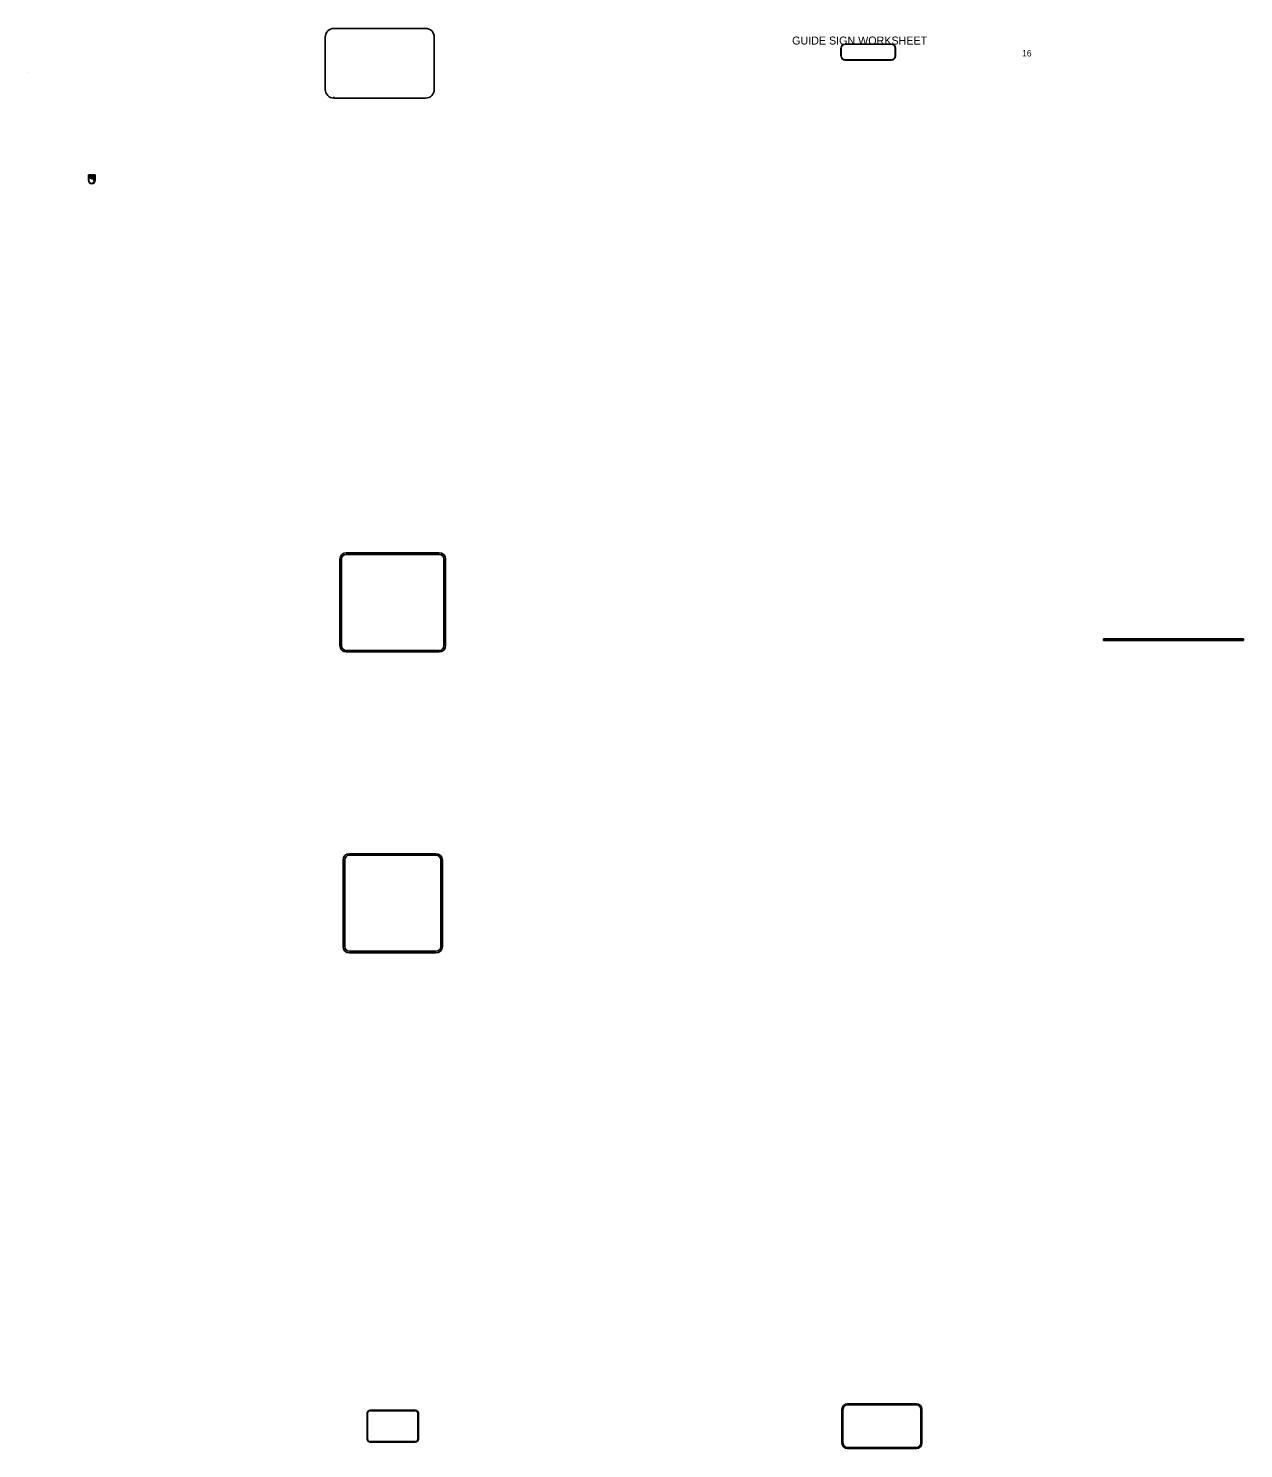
# Model space of a CAD drawing. Extents: x 10268197 to 10268511, y 2141503 to 2142677.
# Drawn here: x 10268312.2 to 10268502, y 2142156.5 to 2142378.2 of the extents above; entities that cross this region are included whole.
import ezdxf

# ---------------------------------------------------------------- set-up
doc = ezdxf.new("R2010")
doc.units = 0
for name, color, linetype in [('AdhocPoint_dp', 7, 'Continuous'), ('GSColorFill', 7, 'Continuous'), ('GSOutline', 7, 'Continuous'), ('TextMisc', 7, 'Continuous'), ('TextShtNo', 7, 'Continuous')]:
    doc.layers.add(name, color=color, linetype=linetype)

msp = doc.modelspace()

# ---------------------------------------------------------------- linework, layer by layer
at = {"layer": 'AdhocPoint_dp'}
msp.add_line((10268312.23, 2142371.28), (10268312.23, 2142371.28), dxfattribs=at)
at = {"layer": 'GSColorFill'}
for p, q in [((10268358.57, 2142376.85), (10268358.57, 2142368.68)), ((10268374.23, 2142378.21), (10268359.93, 2142378.21)), ((10268375.59, 2142368.68), (10268375.59, 2142376.85)), ((10268439.1, 2142375.11), (10268439.1, 2142373.94)), ((10268439.1, 2142375.11), (10268439.1, 2142373.94)), ((10268439.12, 2142373.94), (10268439.12, 2142375.11)), ((10268446.93, 2142375.77), (10268439.77, 2142375.77)), ((10268446.93, 2142375.77), (10268439.77, 2142375.77)), ((10268439.77, 2142375.76), (10268446.93, 2142375.76)), ((10268447.58, 2142375.11), (10268447.58, 2142373.94)), ((10268447.6, 2142373.94), (10268447.6, 2142375.11)), ((10268447.6, 2142373.94), (10268447.6, 2142375.11)), ((10268439.77, 2142373.27), (10268439.77, 2142373.29)), ((10268446.93, 2142373.29), (10268439.77, 2142373.29)), ((10268439.77, 2142373.29), (10268439.77, 2142373.27)), ((10268439.77, 2142373.27), (10268446.93, 2142373.27)), ((10268439.77, 2142373.27), (10268446.93, 2142373.27)), ((10268359.93, 2142367.32), (10268359.93, 2142367.55)), ((10268359.93, 2142367.55), (10268359.93, 2142367.32)), ((10268359.93, 2142367.32), (10268374.23, 2142367.32))]:
    msp.add_line(p, q, dxfattribs=at)
for points in [[(10268321.6, 2142355.3), (10268321.6, 2142354.52)], [(10268321.6, 2142354.52), (10268321.6, 2142355.3)], [(10268321.61, 2142355.3), (10268321.61, 2142354.52)], [(10268322.62, 2142355.3), (10268322.62, 2142355.03), (10268321.64, 2142355.03), (10268321.64, 2142355.3)], [(10268321.64, 2142354.52), (10268321.64, 2142355.01), (10268322.62, 2142355.01), (10268322.62, 2142354.52)], [(10268322.6, 2142355.36), (10268321.66, 2142355.36)], [(10268321.66, 2142355.36), (10268322.6, 2142355.36)], [(10268321.66, 2142355.32), (10268322.13, 2142355.32), (10268322.13, 2142355.34), (10268321.66, 2142355.34)], [(10268321.68, 2142354.96), (10268321.69, 2142354.95)], [(10268321.71, 2142354.88), (10268321.71, 2142354.88)], [(10268321.71, 2142354.88), (10268321.71, 2142354.88)], [(10268321.97, 2142354.91), (10268322.25, 2142354.87)], [(10268322.27, 2142354.89), (10268321.98, 2142354.93)], [(10268322.59, 2142355.34), (10268322.13, 2142355.34), (10268322.13, 2142355.32), (10268322.59, 2142355.32)], [(10268322.28, 2142354.87), (10268322.28, 2142354.87)], [(10268322.31, 2142354.87), (10268322.31, 2142354.87)], [(10268322.33, 2142354.91), (10268322.32, 2142354.92)], [(10268322.32, 2142354.9), (10268322.33, 2142354.89)], [(10268322.34, 2142354.86), (10268322.36, 2142354.76)], [(10268322.38, 2142354.76), (10268322.36, 2142354.87)], [(10268322.39, 2142354.69), (10268322.4, 2142354.67)], [(10268322.42, 2142354.68), (10268322.41, 2142354.7)], [(10268322.64, 2142354.52), (10268322.64, 2142355.3)], [(10268322.65, 2142354.52), (10268322.65, 2142355.3)], [(10268322.65, 2142355.3), (10268322.65, 2142354.52)], [(10268322.13, 2142353.97), (10268322.13, 2142353.99)], [(10268322.13, 2142353.99), (10268322.13, 2142353.97), (10268322.13, 2142353.97)], [(10268322.13, 2142353.95), (10268322.13, 2142353.95)], [(10268322.13, 2142353.95), (10268322.13, 2142353.95)], [(10268322.13, 2142353.95), (10268322.13, 2142353.95)], [(10268322.17, 2142354.65), (10268322.19, 2142354.66)], [(10268322.35, 2142354.19), (10268322.33, 2142354.18)], [(10268322.39, 2142354.17), (10268322.38, 2142354.16)], [(10268322.39, 2142354.14), (10268322.4, 2142354.15)], [(10268322.42, 2142354.64), (10268322.44, 2142354.6)], [(10268322.46, 2142354.61), (10268322.43, 2142354.65)], [(10268322.45, 2142354.57), (10268322.46, 2142354.53)], [(10268322.48, 2142354.53), (10268322.47, 2142354.58)]]:
    msp.add_lwpolyline(points, dxfattribs=at)
for centre, radius, start, end in [((10268359.93, 2142376.85), 1.36, 90, 180), ((10268374.23, 2142376.85), 1.36, 0, 90), ((10268439.77, 2142375.11), 0.667, 90, 180), ((10268439.77, 2142375.11), 0.667, 90, 180), ((10268439.77, 2142375.11), 0.65, 90, 180), ((10268446.93, 2142375.11), 0.667, 0, 90), ((10268446.93, 2142375.11), 0.667, 0, 90), ((10268446.93, 2142375.11), 0.65, 0, 90), ((10268439.77, 2142373.94), 0.667, 180, 270), ((10268439.77, 2142373.94), 0.667, 180, 270), ((10268439.77, 2142373.94), 0.65, 180, 270), ((10268446.93, 2142373.94), 0.667, 270, 0), ((10268446.93, 2142373.94), 0.65, 270, 0), ((10268446.93, 2142373.94), 0.667, 270, 0), ((10268359.93, 2142368.68), 1.36, 180, 270), ((10268374.23, 2142368.68), 1.36, 270, 0)]:
    msp.add_arc(centre, radius, start, end, dxfattribs=at)
for centre, major_axis, start_param, end_param in [((10268321.66, 2142355.29), (0, 0.0703), 0.098213, 1.408003), ((10268321.66, 2142355.29), (0, 0.0705), 0.098082, 1.408221), ((10268321.66, 2142355.29), (0, 0.0529), 0.11327, 1.383001), ((10268321.66, 2142355.29), (0, 0.0294), 0.152033, 1.318544), ((10268321.65, 2142355), (0, 0.026), 4.051262, 4.587994), ((10268322.03, 2142354.81), (0, 0.418), 1.148552, 1.171978), ((10268321.67, 2142354.97), (0, 0.00205), 1.350308, 3.382945), ((10268321.67, 2142354.97), (0, 0.0033), 5.257186, 6.472249), ((10268321.63, 2142354.94), (0, 0.0535), 5.170612, 5.366939), ((10268322.1, 2142358.79), (0, 3.82), 3.0228, 3.102998), ((10268321.68, 2142354.96), (0, 0.00167), 1.876358, 3.458947), ((10268321.68, 2142354.96), (0, 0.0023), 5.006675, 6.675737), ((10268321.68, 2142354.91), (0, 0.00646), 3.672662, 4.871849), ((10268321.69, 2142354.89), (0, 0.0123), 0.633597, 2.648042), ((10268321.69, 2142354.96), (0, 0.00328), 1.878733, 3.108176), ((10268321.69, 2142354.94), (0, 0.00855), 5.256742, 6.115579), ((10268321.69, 2142354.95), (0, 0.00333), 4.486807, 5.309085), ((10268321.78, 2142354.91), (0, 0.0999), 1.186151, 1.539742), ((10268321.7, 2142354.92), (0, 0.0377), 2.867281, 3.188718), ((10268321.7, 2142354.81), (0, 0.0733), 6.061742, 6.254182), ((10268321.69, 2142354.94), (0, 0.032), 5.272311, 5.523753), ((10268322.1, 2142358.79), (0, 3.85), 3.031956, 3.0986), ((10268321.69, 2142354.95), (0, 0.0268), 4.38027, 5.281838), ((10268321.78, 2142354.91), (0, 0.0764), 1.174629, 1.522814), ((10268321.92, 2142355.5), (0, 0.629), 2.775496, 2.836), ((10268321.68, 2142354.91), (0, 0.03), 4.660636, 4.76546), ((10268321.71, 2142354.88), (0, 0.000638), 2.840072, 4.276704), ((10268321.71, 2142354.88), (0, 0.000524), 5.987968, 7.518423), ((10268321.92, 2142355.5), (0, 0.652), 2.795567, 2.837701), ((10268321.76, 2142354.98), (0, 0.081), 2.935797, 3.111869), ((10268321.76, 2142354.98), (0, 0.105), 2.923962, 3.100366), ((10268321.69, 2142354.34), (0, 0.533), 6.086214, 6.156313), ((10268321.69, 2142354.34), (0, 0.556), 6.084521, 6.158258), ((10268321.8, 2142354.92), (0, 0.0309), 2.852504, 3.366789), ((10268321.8, 2142354.92), (0, 0.0544), 2.874985, 3.359529), ((10268321.82, 2142354.81), (0, 0.0792), 6.040706, 6.480942), ((10268321.82, 2142354.81), (0, 0.0557), 6.026184, 6.476458), ((10268321.81, 2142354.7), (0, 0.185), 5.684781, 6.113431), ((10268321.81, 2142354.7), (0, 0.161), 5.697067, 6.119013), ((10268322.01, 2142354.97), (0, 0.181), 2.375, 2.467209), ((10268321.9, 2142354.82), (0, 0.00159), 5.485297, 7.704353), ((10268321.92, 2142354.81), (0, 0.0255), 0.964156, 2.090382), ((10268321.91, 2142354.8), (0, 0.00569), 1.939097, 3.308145), ((10268322.01, 2142354.97), (0, 0.157), 2.362414, 2.445308), ((10268321.9, 2142354.82), (0, 0.0121), 4.628672, 6.022596), ((10268321.89, 2142354.81), (0, 0.0234), 4.312458, 4.790361), ((10268321.93, 2142354.81), (0, 0.0215), 1.284916, 1.908092), ((10268321.9, 2142354.82), (0, 0.0041), 4.221459, 5.929721), ((10268321.91, 2142354.81), (0, 0.00423), 2.162887, 4.05091), ((10268321.89, 2142354.89), (0, 0.104), 3.297928, 3.510473), ((10268321.9, 2142354.82), (0, 0.0356), 4.927168, 5.844494), ((10268321.94, 2142354.77), (0, 0.0259), 6.114599, 6.726558), ((10268321.95, 2142354.91), (0, 0.09), 3.002553, 3.788583), ((10268321.95, 2142354.91), (0, 0.113), 3.077286, 3.764777), ((10268321.98, 2142354.96), (0, 0.0374), 2.044108, 2.116391), ((10268321.99, 2142354.95), (0, 0.0489), 1.626511, 2.63302), ((10268321.95, 2142354.96), (0, 0.012), 4.739475, 5.22955), ((10268321.96, 2142354.95), (0, 0.00667), 4.461638, 5.646624), ((10268321.98, 2142354.96), (0, 0.0139), 1.562078, 2.226686), ((10268321.99, 2142354.95), (0, 0.0254), 1.523898, 2.474336), ((10268322.01, 2142354.81), (0, 0.0327), 0.291413, 0.478416), ((10268322.04, 2142354.83), (0, 0.041), 6.01566, 7.397045), ((10268322.03, 2142354.83), (0, 0.0298), 1.091914, 1.118585), ((10268322.01, 2142354.81), (0, 0.00922), 5.412655, 6.623003), ((10268322.03, 2142354.83), (0, 0.00627), 1.057989, 2.418777), ((10268322.03, 2142354.82), (0, 0.0104), 2.169624, 2.636557), ((10268322.03, 2142354.82), (0, 0.00291), 2.447997, 4.324956), ((10268322.04, 2142354.83), (0, 0.0175), 5.90331, 7.414322), ((10268322.02, 2142354.82), (0, 0.00757), 4.18924, 5.624255), ((10268322.06, 2142354.84), (0, 0.0282), 6.008573, 6.53107), ((10268322.05, 2142354.85), (0, 0.00632), 2.333666, 3.623187), ((10268322.06, 2142354.84), (0, 0.00472), 6.020224, 7.210209), ((10268322.03, 2142354.75), (0, 0.12), 5.371864, 6.001104), ((10268322.03, 2142354.75), (0, 0.0962), 5.382216, 5.999852), ((10268322.03, 2142354.76), (0, 0.0905), 5.020599, 5.276447), ((10268322.14, 2142354.81), (0, 0.0366), 2.049296, 2.415522), ((10268322.03, 2142354.76), (0, 0.114), 5.043581, 5.287393), ((10268322.11, 2142354.76), (0, 0.0216), 4.723898, 5.514452), ((10268322.14, 2142354.81), (0, 0.0132), 2.155604, 2.437858), ((10268322.21, 2142354.77), (0, 0.0926), 1.679569, 1.877594), ((10268322.15, 2142354.75), (0, 0.0211), 1.926422, 2.617636), ((10268322.11, 2142354.76), (0, 0.0451), 4.755633, 5.530169), ((10268322.12, 2142354.7), (0, 0.0371), 4.912404, 5.681954), ((10268322.21, 2142354.77), (0, 0.0691), 1.691953, 1.850237), ((10268322.12, 2142354.7), (0, 0.0606), 4.870438, 5.69492), ((10268322.2, 2142354.71), (0, 0.0466), 1.603254, 2.056889), ((10268322.09, 2142354.65), (0, 0.0815), 4.999681, 5.181626), ((10268322.15, 2142354.67), (0, 0.0125), 4.286383, 5.097358), ((10268322.17, 2142354.66), (0, 0.00829), 1.147713, 2.022718), ((10268322.2, 2142354.71), (0, 0.0231), 1.542583, 2.06345), ((10268322.09, 2142354.65), (0, 0.105), 5.008447, 5.183955), ((10268322.15, 2142354.67), (0, 0.036), 4.58555, 5.059156), ((10268322.15, 2142354.65), (0, 0.0426), 5.101976, 5.271031), ((10268322.27, 2142354.87), (0, 0.0263), 1.495786, 3.039166), ((10268322.19, 2142354.87), (0, 0.0869), 4.732247, 4.878022), ((10268322.28, 2142354.89), (0, 0.00913), 1.352418, 2.01063), ((10268322.26, 2142354.88), (0, 0.00805), 4.379744, 4.814874), ((10268322.28, 2142354.93), (0, 0.0574), 3.035408, 3.204096), ((10268322.27, 2142354.87), (0, 0.00285), 1.109885, 3.045896), ((10268322.28, 2142354.93), (0, 0.0809), 3.036263, 3.109566), ((10268322.28, 2142354.87), (0, 0.0242), 2.680355, 4.018837), ((10268322.28, 2142354.87), (0, 0.000707), 2.226104, 4.018837), ((10268322.28, 2142354.86), (0, 0.00354), 5.664697, 6.296132), ((10268322.3, 2142354.92), (0, 0.00883), 0.407393, 1.224717), ((10268322.29, 2142354.93), (0, 0.00308), 2.554355, 4.582696), ((10268322.32, 2142354.91), (0, 0.0351), 1.15727, 1.990189), ((10268322.27, 2142354.89), (0, 0.0194), 4.289312, 5.031813), ((10268322.32, 2142354.86), (0, 0.0367), 1.060493, 1.42239), ((10268322.28, 2142354.87), (0, 0.00364), 4.143687, 4.652253), ((10268322.33, 2142354.96), (0, 0.0373), 2.364476, 2.623448), ((10268322.3, 2142354.93), (0, 0.00399), 5.525274, 6.621403), ((10268322.28, 2142354.87), (0, 0.0271), 4.143687, 4.589576), ((10268322.29, 2142354.86), (0, 0.0137), 3.974032, 4.188492), ((10268322.31, 2142354.92), (0, 0.0032), 5.726467, 6.786368), ((10268322.31, 2142354.93), (0, 0.0037), 2.763735, 3.701166), ((10268322.27, 2142354.89), (0, 0.0429), 4.289312, 4.979338), ((10268322.32, 2142354.9), (0, 0.00845), 2.088134, 3.055358), ((10268322.32, 2142354.86), (0, 0.0132), 1.060493, 1.394015), ((10268322.32, 2142354.89), (0, 0.0308), 6.107601, 6.199828), ((10268322.31, 2142354.91), (0, 0.0168), 5.307679, 5.799127), ((10268322.34, 2142354.94), (0, 0.0241), 2.956314, 3.451659), ((10268322.34, 2142354.94), (0, 0.0476), 2.956314, 3.025542), ((10268322.42, 2142354.89), (0, 0.0919), 1.581121, 1.86815), ((10268322.35, 2142354.91), (0, 0.00977), 4.497594, 6.497324), ((10268322.42, 2142354.89), (0, 0.0684), 1.39821, 1.880074), ((10268322.41, 2142354.77), (0, 0.0552), 1.756608, 2.347825), ((10268322.3, 2142354.66), (0, 0.103), 5.016392, 5.452977), ((10268322.41, 2142354.77), (0, 0.0317), 1.744904, 2.358794), ((10268322.3, 2142354.66), (0, 0.126), 5.037317, 5.457008), ((10268322.39, 2142354.66), (0, 0.0174), 4.762949, 5.1373), ((10268322.39, 2142354.66), (0, 0.0409), 4.76521, 5.169372), ((10268322.45, 2142354.67), (0, 0.0232), 1.628927, 2.328642), ((10268322.59, 2142355.29), (0, 0.0529), 4.900184, 6.169915), ((10268322.59, 2142355.29), (0, 0.0294), 4.964641, 6.131152), ((10268322.59, 2142355.29), (0, 0.0703), 4.875182, 6.184972), ((10268322.59, 2142355.29), (0, 0.0705), 4.874965, 6.185103), ((10268322.13, 2142354.52), (0, 0.564), 1.570796, 3.141593), ((10268322.13, 2142354.52), (0, 0.564), 1.570796, 3.141593), ((10268322.13, 2142354.52), (0, 0.546), 1.570796, 3.141593), ((10268322.13, 2142354.52), (0, 0.523), 1.570796, 3.141593), ((10268322.13, 2142354.52), (0, 0.546), 3.14161, 4.712389), ((10268322.13, 2142354.52), (0, 0.523), 3.141611, 4.712389), ((10268322.13, 2142354.52), (0, 0.564), 3.141609, 4.712389), ((10268322.13, 2142354.52), (0, 0.564), 3.141609, 4.712389), ((10268322.15, 2142354.65), (0, 0.0191), 5.101976, 5.610981), ((10268322.38, 2142354.19), (0, 0.0543), 1.791653, 2.340122), ((10268322.35, 2142354.17), (0, 0.0176), 2.46822, 2.97436), ((10268322.38, 2142354.19), (0, 0.0308), 1.791653, 2.227493), ((10268322.35, 2142354.14), (0, 0.036), 5.376414, 6.007417), ((10268322.35, 2142354.14), (0, 0.0125), 5.314558, 6.021061), ((10268322.36, 2142354.15), (0, 0.00715), 1.799944, 2.906604), ((10268322.37, 2142354.17), (0, 0.0338), 2.704263, 3.531223), ((10268322.37, 2142354.17), (0, 0.0103), 2.98946, 3.543074), ((10268322.41, 2142354.15), (0, 0.0301), 5.78233, 7.207903), ((10268322.41, 2142354.15), (0, 0.00661), 5.753294, 7.753434), ((10268322.4, 2142354.15), (0, 0.00205), 3.416847, 4.470626), ((10268322.45, 2142354.67), (0, 0.0467), 1.627095, 2.292298), ((10268322.44, 2142354.21), (0, 0.0607), 2.662545, 2.881892), ((10268322.44, 2142354.21), (0, 0.0373), 2.671152, 2.787623), ((10268322.43, 2142354.16), (0, 0.0111), 2.983509, 3.299677), ((10268322.48, 2142353.84), (0, 0.34), 0.131385, 0.184159), ((10268322.48, 2142353.84), (0, 0.317), 0.127189, 0.195375), ((10268322.42, 2142354.58), (0, 0.0255), 4.794307, 5.332356), ((10268322.48, 2142354.16), (0, 0.0455), 1.014577, 1.160734), ((10268322.43, 2142354.21), (0, 0.0339), 3.405622, 3.421225), ((10268322.54, 2142354.59), (0, 0.102), 1.656393, 1.820063), ((10268322.52, 2142354.19), (0, 0.0794), 0.819897, 1.393572), ((10268322.49, 2142354.19), (0, 0.049), 1.41458, 1.781645), ((10268322.43, 2142354.21), (0, 0.0574), 3.374432, 3.63571), ((10268322.42, 2142354.58), (0, 0.0489), 4.795389, 5.336514), ((10268322.52, 2142354.54), (0, 0.0626), 1.731328, 2.298174), ((10268322.49, 2142354.22), (0, 0.0286), 0.515561, 0.875133), ((10268322.48, 2142354.16), (0, 0.022), 0.796146, 1.41392), ((10268322.46, 2142354.16), (0, 0.00633), 3.821556, 4.442761), ((10268322.54, 2142354.59), (0, 0.0784), 1.65682, 1.82178), ((10268322.47, 2142354.49), (0, 0.00243), 4.321398, 5.522959), ((10268322.64, 2142354.27), (0, 0.181), 1.336714, 1.678883), ((10268322.52, 2142354.19), (0, 0.0559), 0.804456, 1.388824), ((10268322.49, 2142354.19), (0, 0.0255), 1.423525, 1.922114), ((10268322.46, 2142354.18), (0, 0.0105), 4.101497, 5.116348), ((10268322.52, 2142354.54), (0, 0.0391), 1.711025, 2.288429), ((10268321.81, 2142354.4), (0, 0.711), 4.587168, 4.842218), ((10268322.51, 2142354.23), (0, 0.0223), 1.391226, 1.671625), ((10268322.21, 2142354.26), (0, 0.294), 4.638315, 4.661489), ((10268322.49, 2142354.22), (0, 0.00515), 0.505292, 0.959827), ((10268322.48, 2142354.23), (0, 0.00426), 3.85142, 4.724901), ((10268322.47, 2142354.49), (0, 0.0259), 4.682902, 5.462261), ((10268322.64, 2142354.27), (0, 0.158), 1.328956, 1.760151), ((10268322.49, 2142354.24), (0, 0.00793), 0.616902, 1.430067), ((10268322.49, 2142354.24), (0, 0.0061), 5.021411, 6.053889), ((10268322.65, 2142354.21), (0, 0.169), 1.349215, 1.424914), ((10268322.48, 2142354.23), (0, 0.0123), 4.104143, 4.720111), ((10268322.49, 2142354.22), (0, 0.00329), 0.723397, 2.164197), ((10268322.47, 2142354.24), (0, 0.0249), 4.100878, 4.619123), ((10268322.49, 2142354.22), (0, 0.00233), 1.92196, 4.222615), ((10268321.81, 2142354.4), (0, 0.735), 4.585352, 4.838269), ((10268322.48, 2142354.24), (0, 0.0177), 4.523068, 4.807624)]:
    msp.add_ellipse(centre, major_axis=major_axis, ratio=0.937499, start_param=start_param, end_param=end_param, dxfattribs=at)
at = {"layer": 'GSOutline'}
for p, q in [((10268360.86, 2142295.34), (10268360.86, 2142281.84)), ((10268361.11, 2142295.34), (10268361.11, 2142281.84)), ((10268376.36, 2142296.34), (10268361.86, 2142296.34)), ((10268376.36, 2142296.09), (10268361.86, 2142296.09)), ((10268377.11, 2142281.84), (10268377.11, 2142295.34)), ((10268377.36, 2142281.84), (10268377.36, 2142295.34)), ((10268480.08, 2142282.92), (10268480.08, 2142282.61)), ((10268501.96, 2142282.92), (10268480.08, 2142282.92)), ((10268480.08, 2142282.61), (10268501.96, 2142282.61)), ((10268501.96, 2142282.61), (10268501.96, 2142282.92)), ((10268361.86, 2142281.09), (10268376.36, 2142281.09)), ((10268361.86, 2142280.84), (10268376.36, 2142280.84)), ((10268361.36, 2142248.35), (10268361.36, 2142234.85)), ((10268361.61, 2142248.35), (10268361.61, 2142234.85)), ((10268375.86, 2142249.35), (10268362.36, 2142249.35)), ((10268375.86, 2142249.1), (10268362.36, 2142249.1)), ((10268376.61, 2142234.85), (10268376.61, 2142248.35)), ((10268376.86, 2142234.85), (10268376.86, 2142248.35)), ((10268362.36, 2142234.1), (10268375.86, 2142234.1)), ((10268362.36, 2142233.85), (10268375.86, 2142233.85)), ((10268365.11, 2142161.96), (10268365.11, 2142157.95)), ((10268365.19, 2142161.96), (10268365.19, 2142157.95)), ((10268372.62, 2142162.46), (10268365.61, 2142162.46)), ((10268372.62, 2142162.37), (10268365.61, 2142162.37)), ((10268373.03, 2142157.95), (10268373.03, 2142161.96)), ((10268373.12, 2142157.95), (10268373.12, 2142161.96)), ((10268439.24, 2142162.58), (10268439.24, 2142157.33)), ((10268439.41, 2142162.58), (10268439.41, 2142157.33)), ((10268450.87, 2142163.45), (10268440.12, 2142163.45)), ((10268450.87, 2142163.29), (10268440.12, 2142163.29)), ((10268451.58, 2142157.33), (10268451.58, 2142162.58)), ((10268451.74, 2142157.33), (10268451.74, 2142162.58)), ((10268365.61, 2142157.54), (10268372.62, 2142157.54)), ((10268365.61, 2142157.45), (10268372.62, 2142157.45)), ((10268440.12, 2142156.62), (10268450.87, 2142156.62)), ((10268440.12, 2142156.45), (10268450.87, 2142156.45))]:
    msp.add_line(p, q, dxfattribs=at)
for centre, radius, start, end in [((10268361.86, 2142295.34), 1, 90, 180), ((10268361.86, 2142295.34), 0.75, 90, 180), ((10268376.36, 2142295.34), 1, 0, 90), ((10268376.36, 2142295.34), 0.75, 0, 90), ((10268361.86, 2142281.84), 1, 180, 270), ((10268361.86, 2142281.84), 0.75, 180, 270), ((10268376.36, 2142281.84), 1, 270, 0), ((10268376.36, 2142281.84), 0.75, 270, 0), ((10268362.36, 2142248.35), 1, 90, 180), ((10268362.36, 2142248.35), 0.75, 90, 180), ((10268375.86, 2142248.35), 1, 0, 90), ((10268375.86, 2142248.35), 0.75, 0, 90), ((10268362.36, 2142234.85), 1, 180, 270), ((10268362.36, 2142234.85), 0.75, 180, 270), ((10268375.86, 2142234.85), 1, 270, 0), ((10268375.86, 2142234.85), 0.75, 270, 0), ((10268365.61, 2142161.96), 0.5, 90, 180), ((10268365.61, 2142161.96), 0.417, 90, 180), ((10268372.62, 2142161.96), 0.5, 0, 90), ((10268372.62, 2142161.96), 0.417, 0, 90), ((10268440.12, 2142162.58), 0.875, 90, 180), ((10268440.12, 2142162.58), 0.708, 90, 180), ((10268450.87, 2142162.58), 0.875, 0, 90), ((10268450.87, 2142162.58), 0.708, 0, 90), ((10268365.61, 2142157.95), 0.5, 180, 270), ((10268365.61, 2142157.95), 0.417, 180, 270), ((10268372.62, 2142157.95), 0.5, 270, 0), ((10268372.62, 2142157.95), 0.417, 270, 0), ((10268440.12, 2142157.33), 0.875, 180, 270), ((10268440.12, 2142157.33), 0.708, 180, 270), ((10268450.87, 2142157.33), 0.875, 270, 0), ((10268450.87, 2142157.33), 0.708, 270, 0)]:
    msp.add_arc(centre, radius, start, end, dxfattribs=at)

# ---------------------------------------------------------------- texts
at = {"layer": 'TextMisc'}
msp.add_text('     GUIDE SIGN WORKSHEET      ', height=1.25, rotation=360, dxfattribs=at).set_placement((10268429.15, 2142375.69))
at = {"layer": 'TextShtNo'}
msp.add_text('16', height=1, rotation=360, dxfattribs=at).set_placement((10268467.37, 2142373.83))

doc.saveas('drawing.dxf')
